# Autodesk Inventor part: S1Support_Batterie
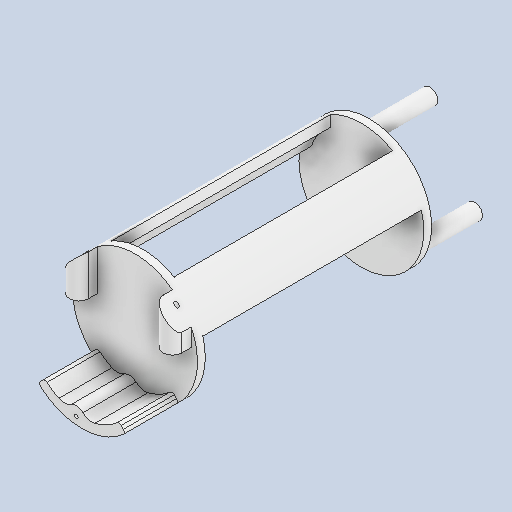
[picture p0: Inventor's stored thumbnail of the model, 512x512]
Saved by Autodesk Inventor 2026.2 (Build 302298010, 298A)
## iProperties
Created: 1601-01
Part Number: S1Support_Batterie
Material: ABS
Document SubType Name: Modeling
Designer: mel
Density: 1.02 g/cm^3
Appearance: white-pw-mt11050
Author: mel
Sending System: SOLIDWORKS 2023
Part Number: Support_Batterie
Last Saved Date: 2025-04-02
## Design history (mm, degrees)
feature "Extru.-Mince1"
node "Plan1"
node "Solide1"
